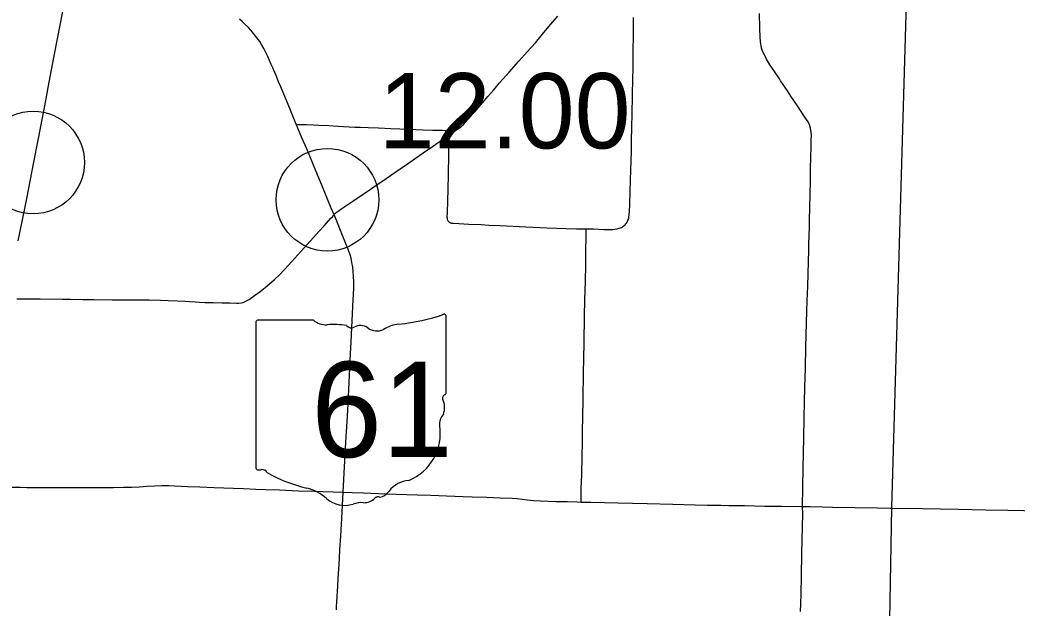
# Model space of a CAD drawing. Extents: x 1813937 to 1948437, y 826606 to 1022856.
# Drawn here: x 1875617 to 1890191, y 914870 to 923462 of the extents above; entities that cross this region are included whole.
import ezdxf

# ---------------------------------------------------------------- set-up
doc = ezdxf.new("R2010")
doc.units = 0
for name, color, linetype in [('Default', 7, 'Continuous'), ('GM_X_County_Road', 7, 'Continuous'), ('GM_X_State_Route', 7, 'Continuous'), ('GM_X_State_Shield', 7, 'Continuous'), ('GM_X_Township', 7, 'Continuous'), ('GM_X_Township_Road', 7, 'Continuous'), ('GM_X_US_Route', 7, 'Continuous')]:
    doc.layers.add(name, color=color, linetype=linetype)

msp = doc.modelspace()

# ---------------------------------------------------------------- linework, layer by layer
at = {"layer": 'Default'}
for centre in [(1875809, 921379), (1880111, 920835)]:
    msp.add_circle(centre, 750, dxfattribs=at)
at = {"layer": 'GM_X_County_Road'}
for points in [[(1880340, 916562), (1880475, 916559), (1880639, 916552), (1880967, 916540), (1881425, 916524), (1881622, 916518), (1881851, 916511), (1882097, 916501), (1882228, 916496), (1882441, 916490), (1882638, 916482), (1882818, 916474), (1882883, 916468), (1883029, 916451), (1883127, 916441), (1883226, 916434), (1883455, 916428), (1883619, 916425), (1883767, 916420), (1883819, 916419)], [(1883819, 916419), (1883963, 916415), (1884160, 916411), (1884357, 916406), (1884570, 916402), (1884783, 916396), (1885160, 916388), (1885488, 916380), (1885668, 916375), (1885864, 916371), (1885979, 916369), (1886209, 916366), (1886504, 916360), (1886750, 916358), (1887055, 916352)], [(1887028, 914817), (1887031, 914931), (1887035, 915078), (1887039, 915341), (1887046, 915669), (1887051, 915866), (1887058, 916244), (1887055, 916352)]]:
    msp.add_lwpolyline(points, dxfattribs=at)
at = {"layer": 'GM_X_State_Route'}
for points in [[(1880340, 916567), (1880381, 917295), (1880389, 917442), (1880403, 917672), (1880413, 917852), (1880427, 918163), (1880448, 918589), (1880456, 918753), (1880467, 918966), (1880489, 919375), (1880495, 919539), (1880497, 919638), (1880494, 919720), (1880489, 919786), (1880481, 919851), (1880470, 919916), (1880456, 919981), (1880443, 920028), (1880416, 920106), (1880387, 920183), (1880324, 920335), (1880238, 920547), (1880209, 920616), (1880167, 920714), (1880029, 921047), (1879940, 921259), (1879808, 921577), (1879736, 921741), (1879680, 921879), (1879656, 921938), (1879630, 922000), (1879561, 922166), (1879473, 922378), (1879428, 922484), (1879398, 922560), (1879361, 922651), (1879322, 922740), (1879316, 922754), (1879303, 922782), (1879291, 922810), (1879239, 922929), (1879212, 922988), (1879182, 923047), (1879148, 923104), (1879121, 923145), (1879083, 923198), (1879033, 923263), (1878991, 923313), (1878958, 923350), (1878911, 923396), (1878863, 923440), (1878825, 923472)], [(1880242, 914845), (1880245, 914894), (1880248, 914959), (1880262, 915188), (1880268, 915302), (1880281, 915511), (1880286, 915592), (1880293, 915723), (1880306, 915919), (1880320, 916181), (1880340, 916558), (1880340, 916562), (1880340, 916567)]]:
    msp.add_lwpolyline(points, dxfattribs=at)
at = {"layer": 'GM_X_State_Shield'}
for p, q in [((1881848, 918022), (1881848, 919128)), ((1879064, 919039), (1879064, 916926)), ((1879907, 919075), (1879091, 919075)), ((1881848, 918022), (1881848, 918022))]:
    msp.add_line(p, q, dxfattribs=at)
for centre, radius, start, end in [((1880856, 921956), 2953, 275.8445, 288.9065), ((1881817, 919132), 31, 351.8621, 97.738), ((1879096, 919043), 32.3, 98.1301, 188.1301), ((1880101, 919320), 313, 231.6195, 271.1119), ((1880205, 917889), 1123, 80.4867, 94.9883), ((1880460, 919054), 90.3, 219.7921, 297.1024), ((1880592, 918810), 188, 54.4667, 119.1411), ((1880834, 919145), 226, 233.8562, 294.8282), ((1881233, 918430), 594, 97.3462, 120.7689), ((1881841, 917941), 48, 107.944, 210.337), ((1881536, 917801), 288, 340.033, 23.6496), ((1881815, 918018), 33.2, 289.6038, 7.7341), ((1881959, 917559), 210, 136.8065, 186.9296), ((1881022, 917419), 739, 292.3089, 8.9858), ((1879096, 916921), 32.5, 171.9584, 258.3066), ((1879101, 917137), 248, 267.339, 280.6039), ((1879152, 916804), 89.5, 29.7484, 93.2717), ((1880282, 918702), 2132, 240.4129, 257.1985), ((1879647, 915976), 667, 47.1842, 75.836), ((1881333, 916332), 404, 94.4031, 142.5768), ((1880368, 916793), 423, 230.7004, 286.2918), ((1880644, 916635), 226, 268.777, 315.5493), ((1880848, 916430), 63.5, 65.7517, 132.6484), ((1880821, 916721), 239, 282.8732, 323.2771), ((1880613, 916062), 348, 85.6951, 111.2099)]:
    msp.add_arc(centre, radius, start, end, dxfattribs=at)
at = {"layer": 'GM_X_Township'}
msp.add_lwpolyline([(1891076, 913698), (1890078, 913562), (1889943, 913553), (1889411, 913481), (1888309, 913332), (1888362, 916340), (1888657, 926560), (1888668, 926924), (1888752, 929651), (1891412, 929604)], dxfattribs=at)
at = {"layer": 'GM_X_Township_Road'}
for points in [[(1881996, 921856), (1882025, 921875), (1882064, 921905), (1882100, 921937), (1882134, 921973), (1882199, 922046), (1882383, 922255), (1882457, 922342), (1882542, 922442), (1882628, 922541), (1882682, 922602), (1882769, 922701), (1882911, 922860), (1883031, 922995), (1883151, 923130), (1883256, 923256), (1883372, 923394), (1883478, 923519)], [(1883893, 920410), (1883910, 920409), (1883933, 920409), (1884002, 920408), (1884150, 920402), (1884232, 920400), (1884281, 920401), (1884313, 920404), (1884346, 920409), (1884377, 920418), (1884393, 920423), (1884408, 920430), (1884422, 920438), (1884436, 920447), (1884448, 920457), (1884461, 920468), (1884471, 920481), (1884481, 920494), (1884490, 920508), (1884498, 920522), (1884504, 920537), (1884510, 920552), (1884515, 920568), (1884518, 920584), (1884523, 920617), (1884527, 920666), (1884530, 920764), (1884536, 920960), (1884545, 921272), (1884554, 921534), (1884558, 921681), (1884561, 921911), (1884565, 922074), (1884570, 922369), (1884574, 922599), (1884579, 922762), (1884580, 922861), (1884580, 923008), (1884583, 923238), (1884586, 923500)], [(1887055, 916352), (1887062, 916636), (1887066, 916915), (1887074, 917357), (1887080, 917653), (1887090, 918095), (1887097, 918374), (1887105, 918686), (1887113, 919030), (1887119, 919210), (1887125, 919358), (1887131, 919571), (1887142, 919932), (1887148, 920096), (1887150, 920194), (1887153, 920309), (1887156, 920440), (1887158, 920538), (1887167, 920915), (1887172, 921112), (1887174, 921292), (1887178, 921456), (1887180, 921604), (1887183, 921702), (1887185, 921784), (1887183, 921817), (1887179, 921850), (1887172, 921883), (1887163, 921915), (1887151, 921945), (1887136, 921975), (1887090, 922044), (1887038, 922123), (1886983, 922205), (1886930, 922285), (1886886, 922350), (1886836, 922426), (1886794, 922489), (1886764, 922534), (1886736, 922574), (1886718, 922601), (1886644, 922708), (1886573, 922817), (1886531, 922887), (1886508, 922931), (1886486, 922975), (1886467, 923020), (1886457, 923050), (1886449, 923082), (1886444, 923114), (1886440, 923146), (1886436, 923211), (1886434, 923342), (1886429, 923555)], [(1879656, 921938), (1879669, 921937), (1879723, 921936), (1879805, 921933), (1879903, 921929), (1879985, 921926), (1880133, 921918), (1880264, 921911), (1880510, 921898), (1880593, 921894), (1880708, 921889), (1880856, 921885), (1881037, 921878), (1881300, 921868), (1881513, 921858), (1881645, 921854), (1881728, 921852), (1881794, 921850), (1881826, 921846), (1881833, 921846), (1881839, 921844), (1881845, 921842), (1881849, 921841)], [(1881849, 921841), (1881854, 921844), (1881857, 921845), (1881861, 921845), (1881889, 921847), (1881924, 921848), (1881942, 921851), (1881959, 921854), (1881978, 921859), (1881981, 921860), (1881983, 921860), (1881985, 921860), (1881986, 921860), (1881987, 921859), (1881990, 921859), (1881992, 921858), (1881996, 921856)], [(1881885, 921781), (1881942, 921821), (1881996, 921856)], [(1880209, 920616), (1880216, 920625), (1880227, 920637), (1880240, 920649), (1880266, 920669), (1880320, 920707), (1880497, 920826), (1880619, 920908), (1880972, 921148), (1881175, 921287), (1881296, 921372), (1881363, 921419), (1881512, 921521), (1881647, 921613), (1881808, 921727), (1881829, 921742)], [(1881829, 921742), (1881885, 921781)], [(1881829, 921742), (1881848, 921733), (1881852, 921731), (1881856, 921729), (1881860, 921727), (1881864, 921724), (1881867, 921721), (1881871, 921717), (1881874, 921712), (1881886, 921697)], [(1881849, 921841), (1881857, 921836), (1881863, 921831), (1881868, 921824), (1881873, 921814), (1881878, 921804), (1881885, 921781)], [(1881885, 921781), (1881886, 921749), (1881886, 921716), (1881886, 921697)], [(1881886, 921697), (1881881, 921487), (1881876, 921208), (1881870, 920979), (1881866, 920831), (1881859, 920634), (1881858, 920585), (1881859, 920569), (1881860, 920561), (1881862, 920553), (1881864, 920544), (1881868, 920537), (1881871, 920531), (1881876, 920523), (1881881, 920518), (1881887, 920512), (1881895, 920506), (1881901, 920503), (1881907, 920499), (1881916, 920496), (1881923, 920494), (1881932, 920493), (1881940, 920491), (1881948, 920491), (1882030, 920487), (1882177, 920480), (1882358, 920472), (1882472, 920466), (1882636, 920459), (1883013, 920440), (1883324, 920426), (1883602, 920414), (1883753, 920411), (1883864, 920410), (1883878, 920410), (1883893, 920410)], [(1875570, 919389), (1875750, 919387), (1875914, 919387), (1876242, 919384), (1876357, 919382), (1876538, 919380), (1876702, 919377), (1876964, 919375), (1877325, 919373), (1877506, 919371), (1877670, 919368), (1877785, 919364), (1877916, 919359), (1878031, 919354), (1878096, 919350), (1878178, 919345), (1878243, 919340), (1878325, 919336), (1878440, 919332), (1878571, 919330), (1878686, 919327), (1878784, 919324), (1878817, 919325), (1878849, 919329), (1878880, 919336), (1878910, 919347), (1878939, 919361), (1878967, 919378), (1879047, 919435), (1879126, 919494), (1879203, 919554), (1879266, 919607), (1879340, 919672), (1879410, 919740), (1879478, 919811), (1879589, 919932), (1879677, 920029), (1879766, 920126), (1879810, 920175), (1879909, 920285), (1879985, 920370), (1880062, 920455), (1880163, 920564), (1880188, 920590), (1880199, 920603), (1880209, 920616)], [(1883819, 916419), (1883819, 916454), (1883820, 916485), (1883822, 916617), (1883828, 916814), (1883834, 917092), (1883838, 917289), (1883840, 917469), (1883844, 917649), (1883850, 917928), (1883855, 918305), (1883858, 918518), (1883863, 918747), (1883871, 919140), (1883876, 919370), (1883882, 919648), (1883886, 919878), (1883890, 920074), (1883892, 920304), (1883893, 920371), (1883893, 920389), (1883893, 920402), (1883893, 920410)], [(1875473, 916637), (1875621, 916634), (1875719, 916633), (1875834, 916632), (1875998, 916631), (1876162, 916631), (1876310, 916630), (1876523, 916629), (1876769, 916629), (1876983, 916631), (1877131, 916634), (1877245, 916637), (1877360, 916642), (1877475, 916650), (1877589, 916657), (1877687, 916660), (1877786, 916658), (1878065, 916648), (1878245, 916641), (1878458, 916633), (1878737, 916622), (1878885, 916616), (1879065, 916609), (1879213, 916603), (1879409, 916596), (1879688, 916583), (1879918, 916576), (1880049, 916572), (1880340, 916562)], [(1887055, 916352), (1887168, 916351), (1887348, 916348), (1887496, 916345), (1887824, 916338), (1888152, 916333), (1888333, 916330), (1888346, 916330)], [(1888346, 916330), (1888809, 916322), (1889334, 916313), (1889728, 916306), (1890056, 916299), (1890761, 916284), (1891090, 916278), (1891124, 916277)]]:
    msp.add_lwpolyline(points, dxfattribs=at)
at = {"layer": 'GM_X_US_Route'}
msp.add_lwpolyline([(1875593, 920235), (1875682, 920685), (1875720, 920879), (1875815, 921362), (1875889, 921732), (1876001, 922312), (1876031, 922473), (1876080, 922731), (1876119, 922940), (1876208, 923408), (1876266, 923714), (1876290, 923843), (1876353, 924181), (1876390, 924375), (1876432, 924600), (1876463, 924762), (1876476, 924828), (1876499, 924955)], dxfattribs=at)

# ---------------------------------------------------------------- texts
at = {"layer": 'Default'}
msp.add_text('12.00', height=1100, dxfattribs=at).set_placement((1880861, 921585))
at = {"layer": 'GM_X_State_Shield'}
msp.add_text('61', height=1392.2, dxfattribs=at).set_placement((1879874, 917075))

doc.saveas('drawing.dxf')
